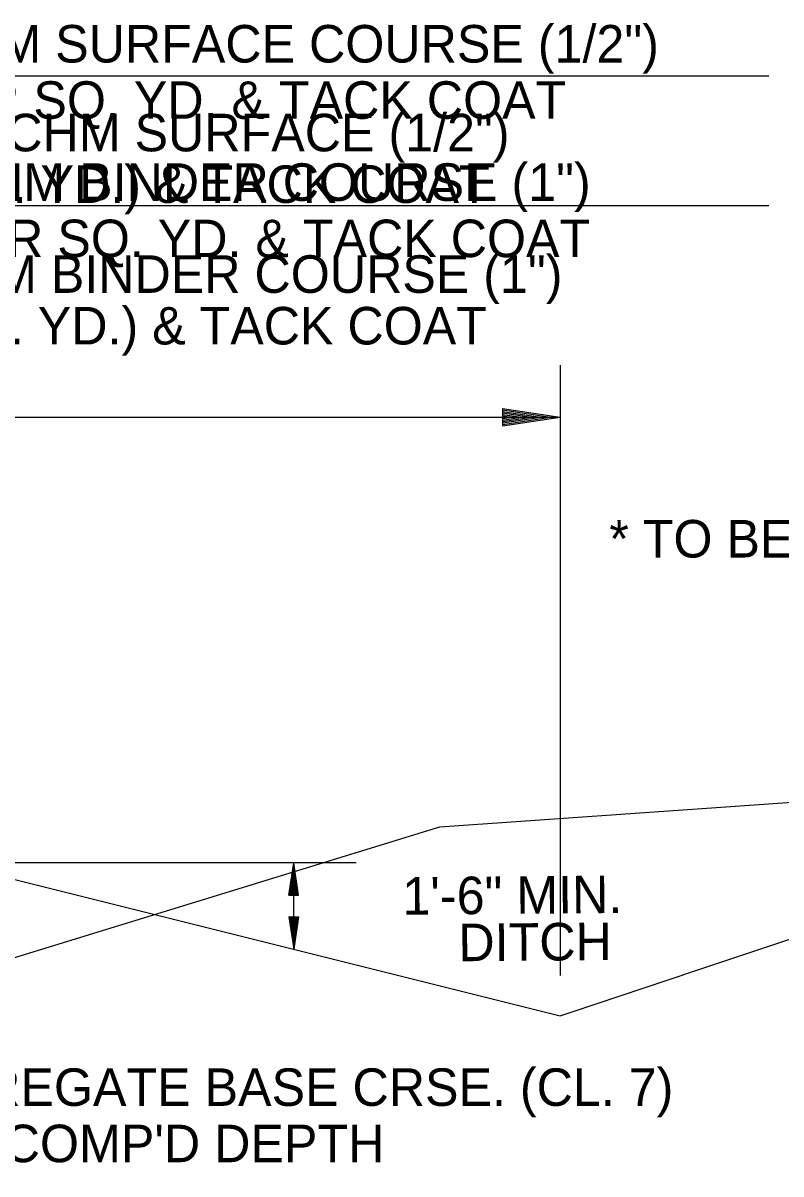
# Model space of a CAD drawing. Extents: x 1373719 to 1374161, y 379835 to 380167.
# Drawn here: x 1373986.78 to 1373999.9, y 380106.89 to 380126.83 of the extents above; entities that cross this region are included whole.
import ezdxf

# ---------------------------------------------------------------- set-up
doc = ezdxf.new("R2010")
doc.units = 0
for name, color, linetype in [('Agg Base Course Text', 7, 'Continuous'), ('Ditch Text - off', 7, 'Continuous'), ('GREEN_TXT', 7, 'Continuous'), ('Pavement Layers', 7, 'Continuous'), ('T_Drafting', 7, 'Continuous'), ('Text 1', 7, 'Continuous')]:
    doc.layers.add(name, color=color, linetype=linetype)

msp = doc.modelspace()

# ---------------------------------------------------------------- linework, layer by layer
for p, q in [((1373996.075, 380109.635), (1374008.976, 380113.935)), ((1373980.012, 380113.65), (1373996.075, 380109.635))]:
    msp.add_line(p, q)
at = {"layer": 'Ditch Text - off'}
for p, q in [((1373985.463, 380112.288), (1373992.542, 380112.288)), ((1373991.377, 380111.726), (1373991.461, 380112.284)), ((1373991.544, 380111.726), (1373991.461, 380112.284)), ((1373991.463, 380110.788), (1373991.463, 380112.288)), ((1373991.391, 380111.726), (1373991.461, 380112.191)), ((1373991.405, 380111.726), (1373991.461, 380112.095)), ((1373991.53, 380111.726), (1373991.461, 380112.191)), ((1373991.516, 380111.726), (1373991.461, 380112.095)), ((1373991.419, 380111.726), (1373991.461, 380112.002)), ((1373991.433, 380111.726), (1373991.461, 380111.907)), ((1373991.502, 380111.726), (1373991.461, 380112.002)), ((1373991.488, 380111.726), (1373991.461, 380111.907)), ((1373991.377, 380111.726), (1373991.544, 380111.726)), ((1373991.447, 380111.726), (1373991.461, 380111.814)), ((1373991.474, 380111.726), (1373991.461, 380111.814)), ((1373991.379, 380111.346), (1373991.463, 380110.788)), ((1373991.379, 380111.346), (1373991.547, 380111.346)), ((1373991.393, 380111.346), (1373991.463, 380110.881)), ((1373991.407, 380111.346), (1373991.463, 380110.977)), ((1373991.421, 380111.346), (1373991.463, 380111.07)), ((1373991.436, 380111.346), (1373991.463, 380111.165)), ((1373991.45, 380111.346), (1373991.463, 380111.258)), ((1373991.547, 380111.346), (1373991.463, 380110.788)), ((1373991.49, 380111.346), (1373991.463, 380111.165)), ((1373991.519, 380111.346), (1373991.463, 380110.977)), ((1373991.533, 380111.346), (1373991.463, 380110.881)), ((1373991.505, 380111.346), (1373991.463, 380111.07)), ((1373991.476, 380111.346), (1373991.463, 380111.258))]:
    msp.add_line(p, q, dxfattribs=at)
at = {"layer": 'GREEN_TXT'}
for p, q in [((1373996.075, 380120.901), (1373996.075, 380110.33)), ((1373995.075, 380120.151), (1373996.075, 380120.001)), ((1373995.075, 380120.151), (1373995.075, 380119.851)), ((1373995.075, 380120.126), (1373995.908, 380120.001)), ((1373995.075, 380120.101), (1373995.736, 380120.001)), ((1373995.075, 380120.076), (1373995.57, 380120.001)), ((1373995.075, 380120.05), (1373995.4, 380120.001)), ((1373975.044, 380120.001), (1373996.075, 380120.001)), ((1373995.075, 380120.025), (1373995.233, 380120.001)), ((1373995.075, 380119.851), (1373996.075, 380120.001)), ((1373995.075, 380119.952), (1373995.4, 380120.001)), ((1373995.075, 380119.902), (1373995.736, 380120.001)), ((1373995.075, 380119.876), (1373995.908, 380120.001)), ((1373995.075, 380119.927), (1373995.57, 380120.001)), ((1373995.075, 380119.978), (1373995.233, 380120.001))]:
    msp.add_line(p, q, dxfattribs=at)
at = {"layer": 'T_Drafting'}
msp.add_lwpolyline([(1373907.987, 380106.564), (1373924.533, 380106.487), (1373943.45, 380108.654), (1373953.585, 380112.614), (1373955.026, 380112.615), (1373964.851, 380112.903), (1373975.028, 380112.689), (1373976.603, 380112.615), (1373985.688, 380110.353), (1373993.989, 380112.909), (1374008.917, 380113.95), (1374025.023, 380113.95)], dxfattribs=at)
at = {"layer": 'Text 1'}
for p, q in [((1373979.15, 380125.916), (1373999.687, 380125.916)), ((1373979.254, 380123.665), (1373999.687, 380123.665))]:
    msp.add_line(p, q, dxfattribs=at)

# ---------------------------------------------------------------- texts
at = {"layer": 'Agg Base Course Text'}
for s, p in [('AGGREGATE BASE CRSE. (CL. 7)', (1373984.171, 380108.073)), ("VAR. COMP'D DEPTH", (1373984.171, 380107.098))]:
    msp.add_text(s, height=0.65, dxfattribs=at).set_placement(p)
at = {"layer": 'Ditch Text - off'}
for s, p in [('1\'-6" MIN.', (1373993.345, 380111.384)), ('DITCH', (1373994.314, 380110.578))]:
    msp.add_text(s, height=0.65, rotation=0.4545, dxfattribs=at).set_placement(p)
at = {"layer": 'GREEN_TXT'}
for s, p in [('2\'-1 1/2" ACHM SURFACE (1/2")', (1373982.484, 380124.606)), ('(220 LBS./SQ. YD.) & TACK COAT', (1373981.233, 380123.712)), ('2\'-2 3/4" ACHM BINDER COURSE (1")', (1373981.034, 380122.155)), ('(330 LBS./SQ. YD.) & TACK COAT', (1373981.185, 380121.261))]:
    msp.add_text(s, height=0.65, dxfattribs=at).set_placement(p)
at = {"layer": 'Pavement Layers'}
msp.add_text('* TO BE USED IF AND WHERE DIRECTED BY THE ENGINEER', height=0.65, dxfattribs=at).set_placement((1373996.924, 380117.571))
at = {"layer": 'Text 1'}
for s, p in [('5\'-1 1/2" ACHM SURFACE COURSE (1/2")', (1373981.109, 380126.144)), ('220 LBS. PER SQ. YD. & TACK COAT', (1373981.109, 380125.169)), ('5\'-2 3/4" ACHM BINDER COURSE (1")', (1373981.523, 380123.748)), ('330 LBS. PER SQ. YD. & TACK COAT', (1373981.523, 380122.773))]:
    msp.add_text(s, height=0.65, dxfattribs=at).set_placement(p)

doc.saveas('drawing.dxf')
